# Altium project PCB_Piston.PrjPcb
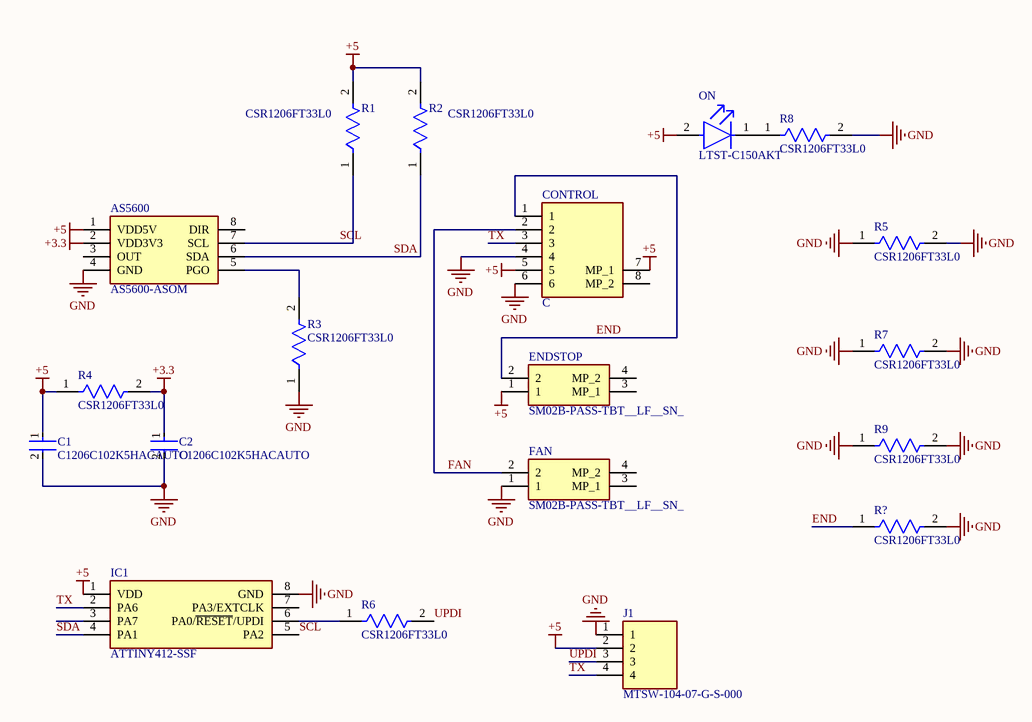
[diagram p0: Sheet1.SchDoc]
1 sheet, 19 parts. Net scope: global (net labels, ports and power ports of the same name join across sheets).
Board file: PCB1.PcbDoc

## Sheet Sheet1.SchDoc
size A; SheetNumber: 1; SheetTotal: 1

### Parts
AS5600  AS5600-ASOM  [SOIC127P600X175-8N]
C1  C1206C102K5HACAUTO  [FP-C1206C-EB-MFG]
C2  C1206C102K5HACAUTO  [FP-C1206C-EB-MFG]
CONTROL  C  [SM06BZESSTBLFSN]
ENDSTOP  SM02B-PASS-TBT__LF__SN_  [SM02BPASSTBTLFSN]
FAN  SM02B-PASS-TBT__LF__SN_  [SM02BPASSTBTLFSN]
IC1  ATTINY412-SSF  [SOIC127P600X175-8N]
J1  MTSW-104-07-G-S-000  [HDRV4W64P0X254_1X4_1016X254X864P]
ON  LTST-C150AKT  [FP-LTST-C150AKT-MFG]
R1  CSR1206FT33L0  [FP-CSR1206-MFG]
R2  CSR1206FT33L0  [FP-CSR1206-MFG]
R3  CSR1206FT33L0  [FP-CSR1206-MFG]
R4  CSR1206FT33L0  [FP-CSR1206-MFG]
R5  CSR1206FT33L0  [FP-CSR1206-MFG]
R6  CSR1206FT33L0  [FP-CSR1206-MFG]
R7  CSR1206FT33L0  [FP-CSR1206-MFG]
R8  CSR1206FT33L0  [FP-CSR1206-MFG]
R9  CSR1206FT33L0  [FP-CSR1206-MFG]
R?  CSR1206FT33L0  [FP-CSR1206-MFG]

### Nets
+3.3: AS5600.2(VDD3V3) C2.1 R4.2
+5: AS5600.1(VDD5V) C1.1 CONTROL.5 CONTROL.7(MP_1) ENDSTOP.1 IC1.1(VDD) J1.2 ON.2(A) R1.2 R2.2 R4.1
GND: AS5600.4(GND) C1.2 C2.2 CONTROL.4 CONTROL.6 FAN.1 IC1.8(GND) J1.1 R3.1 R5.1 R5.2 R7.1 R7.2 R8.2 R9.1 R9.2 R?.2
END: CONTROL.1 ENDSTOP.2 R?.1
FAN: CONTROL.2 FAN.2
SCL: AS5600.7(SCL) IC1.5(PA2) R1.1
SDA: AS5600.6(SDA) IC1.4(PA1) R2.1
TX: CONTROL.3 IC1.2(PA6) J1.4
UPDI: J1.3 R6.2
NetAS5600_5: AS5600.5(PGO) R3.2
NetIC1_6: IC1.6(PA0/~{RESET}/UPDI) R6.1
NetON_1: ON.1(C) R8.1

Not connected (* = marked no-connect by the designer): AS5600 3(OUT) 8(DIR); CONTROL 8(MP_2); ENDSTOP 3(MP_1) 4(MP_2); FAN 3(MP_1) 4(MP_2); IC1 3(PA7) 7(PA3/EXTCLK)

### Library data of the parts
AS5600 = AS5600-ASOM: Integrated Circuit; Manufacturer_Name: ams OSRAM
C1 C2 = CMP-03020-003638-1: C1206 1,000 pF X8R 10.00% 50 V; Manufacturer: KEMET; Material: Ceramic; Temperature Coefficient: 15%; Automotive Grade: Grade 0; Tolerance: 0.1; Voltage Rating: 50 V
CONTROL = SM06B-ZESS-TB_LF__SN_: Connector; Manufacturer_Name: JST (JAPAN SOLDERLESS TERMINALS); Manufacturer_Part_Number: SM06B-ZESS-TB(LF)(SN)
ENDSTOP FAN = SM02B-PASS-TBT__LF__SN_: Connector; Manufacturer_Name: JST (JAPAN SOLDERLESS TERMINALS); Manufacturer_Part_Number: SM02B-PASS-TBT (LF)(SN)
IC1 = ATTINY412-SSF: Integrated Circuit; Manufacturer_Name: Microchip
J1 = MTSW-104-07-G-S-000: Connector; Manufacturer_Name: SAMTEC
ON = CMP-22017-000004-1: LED AMBER CLEAR SMD; Manufacturer: Lite-On; Luminous Intensity: 6mcd; Viewing Angle: 130°; Wavelength: 602nm; Reverse Voltage: 5V; Forward Current: 30mA; Led Orientation: Top View; Power Dissipation: 100mW; Peak Emmision Wavelength: 610nm; Forward Voltage: 2.1V
R1-R9 R? = CMP-26527-002831-1: General Purpose Thick Film Chip Resistor, 1206, 33mΩ, 1%, 0.5W; Resistance: 33mR; Temperature Coefficient: 100ppm/°C; Max Power Dissipation: 500mW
